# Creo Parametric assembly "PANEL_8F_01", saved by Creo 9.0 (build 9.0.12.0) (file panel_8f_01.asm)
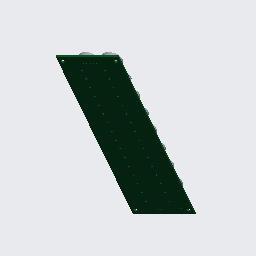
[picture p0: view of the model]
Units: millimeter Newton Second (mmNs); MM, TONNE, SECS

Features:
  1. coordinate system "PANEL_8F_01"
  2. imported feature "Import Feature id 4"
  3. component "PCB_8F"
  4. component "TX_8F_T1"
  5. component "TX_8F_T1"
  6. component "TX_8F_T1"
  7. component "TX_8F_T1"
  8. component "TX_8F_T1"
  9. component "TX_8F_T1"
  10. component "TX_8F_T1"
  11. component "TX_8F_T1"
  12. component "TX_8F_T1"
  13. component "TX_8F_T1"
  14. component "TX_8F_T1"
  15. component "TX_8F_T1"
  16. component "TX_8F_T1"
  17. component "TX_8F_T1"
  18. component "TX_8F_T1"
  19. component "TX_8F_T1"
